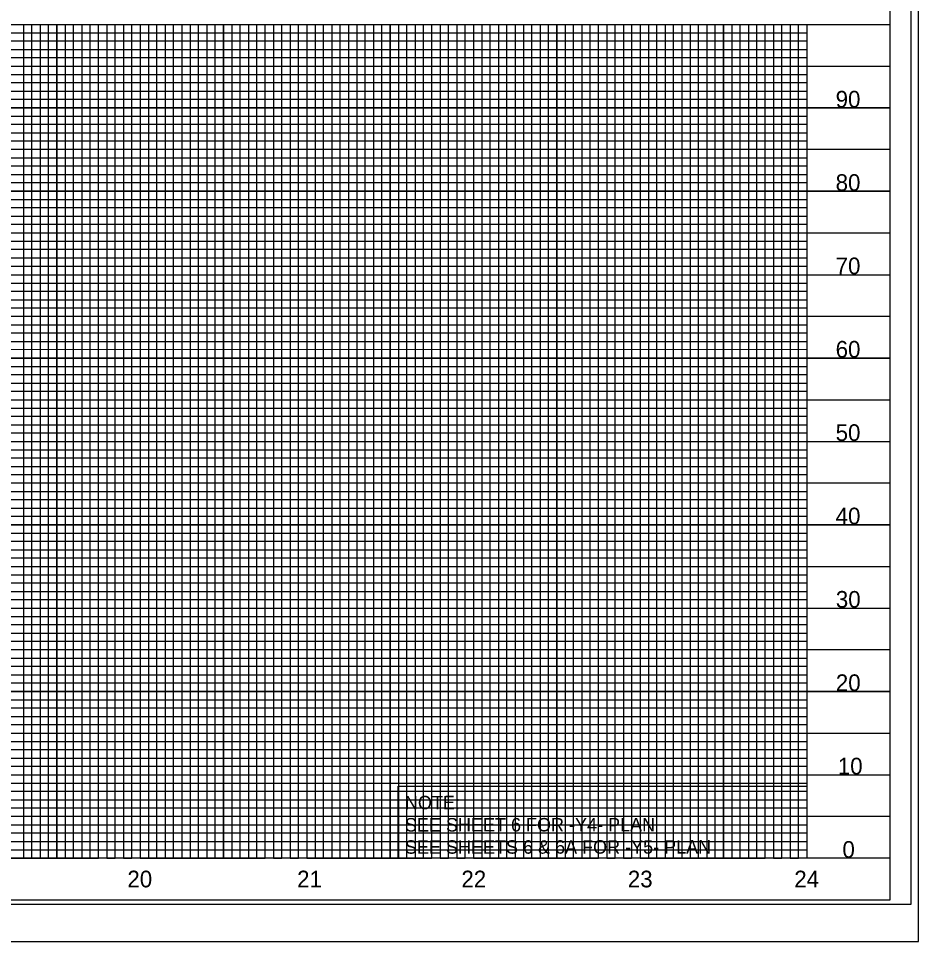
# Model space of a CAD drawing. Extents: x 2186391 to 2188300, y 74582 to 75682.
# Drawn here: x 2187535 to 2188075, y 74582 to 75136 of the extents above; entities that cross this region are included whole.
import ezdxf

# ---------------------------------------------------------------- set-up
doc = ezdxf.new("R2010")
doc.units = 0
for name, color, linetype in [('Exist Structure Minor Culvert Topo', 7, 'Continuous'), ('Exist Structure Minor Culvert Topo Terminator', 7, 'Continuous'), ('Old_Level_1', 7, 'Continuous'), ('Old_Level_11', 7, 'Continuous'), ('Old_Level_2', 7, 'Continuous'), ('Old_Level_3', 7, 'Continuous'), ('Scratch_Level_0', 7, 'Continuous'), ('Sheet Border Standard 30in CELL', 7, 'Continuous'), ('Sheet Cutting Line CELL', 7, 'Continuous'), ('Sheet Plot Border Outside CELL', 7, 'Continuous'), ('Sheet Sticker Exception Certification CELL', 7, 'Continuous'), ('Sheet Sticker Incomplete CELL', 7, 'Continuous'), ('Sheet Sticker Preliminary CELL', 7, 'Continuous')]:
    doc.layers.add(name, color=color, linetype=linetype)

msp = doc.modelspace()

# ---------------------------------------------------------------- linework, layer by layer
at = {"layer": 'Exist Structure Minor Culvert Topo Terminator'}
msp.add_lwpolyline([(2187762.5, 74675.46), (2188007.69, 74675.46), (2188007.69, 74632.28), (2187762.5, 74632.28)], close=True, dxfattribs=at)
at = {"layer": 'Old_Level_11'}
for p, q in [((2186557.69, 75132.28), (2188057.58, 75132.28)), ((2187557.69, 75132.28), (2187557.69, 74632.28)), ((2187607.69, 75132.28), (2187607.69, 74632.28)), ((2187657.69, 75132.28), (2187657.69, 74632.28)), ((2187707.69, 75132.28), (2187707.69, 74632.28)), ((2187757.69, 75132.28), (2187757.69, 74632.28)), ((2187807.69, 75132.28), (2187807.69, 74632.28)), ((2187857.69, 75132.28), (2187857.69, 74632.28)), ((2187907.69, 75132.28), (2187907.69, 74632.28)), ((2187957.69, 75132.28), (2187957.69, 74632.28)), ((2188007.69, 75132.28), (2188007.69, 74632.28)), ((2186557.69, 75082.28), (2188057.58, 75082.28)), ((2186557.69, 75032.28), (2188057.58, 75032.28)), ((2186557.69, 74982.28), (2188057.58, 74982.28)), ((2186557.69, 74932.28), (2188057.58, 74932.28)), ((2186557.69, 74882.28), (2188057.58, 74882.28)), ((2186557.69, 74832.28), (2188057.58, 74832.28)), ((2186557.69, 74782.28), (2188057.58, 74782.28)), ((2186557.69, 74732.28), (2188057.58, 74732.28)), ((2186557.69, 74682.28), (2188057.58, 74682.28))]:
    msp.add_line(p, q, dxfattribs=at)
at = {"layer": 'Old_Level_2'}
for points in [[(2187532.69, 74632.28), (2187582.69, 74632.28), (2187582.69, 75132.28), (2187632.69, 75132.28), (2187632.69, 74632.28), (2187682.69, 74632.28), (2187682.69, 75132.28), (2187732.69, 75132.28), (2187732.69, 74632.28), (2187782.69, 74632.28), (2187782.69, 75132.28), (2187832.69, 75132.28), (2187832.69, 74632.28), (2187882.69, 74632.28), (2187882.69, 75132.28), (2187932.69, 75132.28), (2187932.69, 74632.28), (2187982.69, 74632.28), (2187982.69, 75132.28)], [(2186557.69, 75107.28), (2188057.69, 75107.28)], [(2188057.69, 75057.28), (2186557.69, 75057.28), (2186557.69, 75007.28), (2188057.69, 75007.28)], [(2188057.69, 74957.28), (2186557.69, 74957.28), (2186557.69, 74907.28), (2188057.69, 74907.28)], [(2188057.69, 74857.28), (2186557.69, 74857.28), (2186557.69, 74807.28), (2188057.69, 74807.28)], [(2188057.69, 74757.28), (2186557.69, 74757.28), (2186557.69, 74707.28), (2188057.69, 74707.28)], [(2188057.69, 74657.28), (2186557.69, 74657.28)]]:
    msp.add_lwpolyline(points, dxfattribs=at)
at = {"layer": 'Scratch_Level_0'}
msp.add_line((2186390.69, 74582.28), (2188074.69, 74582.28), dxfattribs=at)
at = {"layer": 'Sheet Border Standard 30in CELL'}
msp.add_lwpolyline([(2186607.69, 75132.28), (2188007.69, 75132.28), (2188007.69, 74632.28), (2186607.69, 74632.28)], close=True, dxfattribs=at)
msp.add_lwpolyline([(2186607.69, 75132.28), (2188007.69, 75132.28), (2188007.69, 74632.28), (2186607.69, 74632.28)], close=True, dxfattribs=at)
at = {"layer": 'Sheet Cutting Line CELL'}
for p, q in [((2186557.69, 75132.28), (2188057.69, 75132.28)), ((2188057.69, 74632.28), (2186557.69, 74632.28)), ((2186557.69, 74607.28), (2188057.69, 74607.28))]:
    msp.add_line(p, q, dxfattribs=at)
msp.add_lwpolyline([(2188057.69, 75657.28), (2186557.69, 75657.28), (2186557.69, 74607.28), (2188057.69, 74607.28)], close=True, dxfattribs=at)
at = {"layer": 'Sheet Plot Border Outside CELL'}
for p, q in [((2186607.69, 75127.28), (2188007.69, 75127.28)), ((2188007.69, 75122.28), (2186607.69, 75122.28)), ((2186607.69, 75117.28), (2188007.69, 75117.28)), ((2188007.69, 75112.28), (2186607.69, 75112.28)), ((2186607.69, 75102.28), (2188007.69, 75102.28)), ((2188007.69, 75097.28), (2186607.69, 75097.28)), ((2186607.69, 75092.28), (2188007.69, 75092.28)), ((2188007.69, 75087.28), (2186607.69, 75087.28)), ((2186607.69, 75077.28), (2188007.69, 75077.28)), ((2188007.69, 75072.28), (2186607.69, 75072.28)), ((2186607.69, 75067.28), (2188007.69, 75067.28)), ((2188007.69, 75062.28), (2186607.69, 75062.28)), ((2186607.69, 75052.28), (2188007.69, 75052.28)), ((2188007.69, 75047.28), (2186607.69, 75047.28)), ((2186607.69, 75042.28), (2188007.69, 75042.28)), ((2188007.69, 75037.28), (2186607.69, 75037.28)), ((2186607.69, 75027.28), (2188007.69, 75027.28)), ((2188007.69, 75022.28), (2186607.69, 75022.28)), ((2186607.69, 75017.28), (2188007.69, 75017.28)), ((2188007.69, 75012.28), (2186607.69, 75012.28)), ((2186607.69, 75002.28), (2188007.69, 75002.28)), ((2188007.69, 74997.28), (2186607.69, 74997.28)), ((2186607.69, 74992.28), (2188007.69, 74992.28)), ((2188007.69, 74987.28), (2186607.69, 74987.28)), ((2186607.69, 74977.28), (2188007.69, 74977.28)), ((2188007.69, 74972.28), (2186607.69, 74972.28)), ((2186607.69, 74967.28), (2188007.69, 74967.28)), ((2188007.69, 74962.28), (2186607.69, 74962.28)), ((2186607.69, 74952.28), (2188007.69, 74952.28)), ((2188007.69, 74947.28), (2186607.69, 74947.28)), ((2186607.69, 74942.28), (2188007.69, 74942.28)), ((2188007.69, 74937.28), (2186607.69, 74937.43)), ((2186607.69, 74927.28), (2188007.69, 74927.28)), ((2188007.69, 74922.28), (2186607.69, 74922.28)), ((2186607.69, 74917.28), (2188007.69, 74917.28)), ((2188007.69, 74912.28), (2186607.69, 74912.28)), ((2186607.69, 74902.28), (2188007.69, 74902.28)), ((2188007.69, 74897.28), (2186607.69, 74897.28)), ((2186607.69, 74892.28), (2188007.69, 74892.28)), ((2188007.69, 74887.28), (2186607.69, 74887.28)), ((2186607.69, 74877.28), (2188007.69, 74877.28)), ((2188007.69, 74872.28), (2186607.69, 74872.28)), ((2186607.69, 74867.28), (2188007.69, 74867.28)), ((2188007.69, 74862.28), (2186607.69, 74862.28)), ((2186607.69, 74852.28), (2188007.69, 74852.28)), ((2188007.69, 74847.28), (2186607.69, 74847.28)), ((2186607.69, 74842.28), (2188007.69, 74842.28)), ((2188007.69, 74837.28), (2186607.69, 74837.28)), ((2186607.69, 74827.28), (2188007.69, 74827.28)), ((2188007.69, 74822.28), (2186607.69, 74822.28)), ((2186607.69, 74817.28), (2188007.69, 74817.28)), ((2188007.69, 74812.28), (2186607.69, 74812.28)), ((2186607.69, 74802.28), (2188007.69, 74802.28)), ((2188007.69, 74797.28), (2186607.69, 74797.28)), ((2186607.69, 74792.28), (2188007.69, 74792.28)), ((2188007.69, 74787.28), (2186607.69, 74787.28)), ((2186607.69, 74777.28), (2188007.69, 74777.28)), ((2188007.69, 74772.28), (2186607.69, 74772.28)), ((2186607.69, 74767.28), (2188007.69, 74767.28)), ((2188007.69, 74762.28), (2186607.69, 74762.28)), ((2186607.69, 74752.28), (2188007.69, 74752.28)), ((2188007.69, 74747.28), (2186607.69, 74747.28)), ((2186607.69, 74742.28), (2188007.69, 74742.28)), ((2188007.69, 74737.28), (2186607.69, 74737.28)), ((2186607.69, 74727.28), (2188007.69, 74727.28)), ((2188007.69, 74722.28), (2186607.69, 74722.28)), ((2186607.69, 74717.28), (2188007.69, 74717.28)), ((2188007.69, 74712.28), (2186607.69, 74712.28)), ((2186607.69, 74702.28), (2188007.69, 74702.28)), ((2188007.69, 74697.28), (2186607.69, 74697.28)), ((2186607.69, 74692.28), (2188007.69, 74692.28)), ((2188007.69, 74687.28), (2186607.69, 74687.28)), ((2186607.69, 74677.28), (2188007.69, 74677.28)), ((2188007.69, 74672.28), (2186607.69, 74672.28)), ((2186607.69, 74667.28), (2188007.69, 74667.28)), ((2188007.69, 74662.28), (2186607.69, 74662.28)), ((2186607.69, 74652.28), (2188007.69, 74652.28)), ((2188007.69, 74647.28), (2186607.69, 74647.28)), ((2186607.69, 74642.28), (2188007.69, 74642.28)), ((2186607.69, 74637.28), (2188007.69, 74637.28)), ((2188007.69, 74637.28), (2188007.69, 74637.28))]:
    msp.add_line(p, q, dxfattribs=at)
for points in [[(2187527.69, 75132.28), (2187537.69, 75132.28), (2187537.69, 74632.28), (2187542.69, 74632.28), (2187542.69, 75132.28), (2187547.69, 75132.28), (2187547.69, 74632.28), (2187552.69, 74632.28), (2187552.69, 75132.28), (2187562.69, 75132.28), (2187562.69, 74632.28), (2187567.69, 74632.28), (2187567.69, 75132.28), (2187572.69, 75132.28), (2187572.69, 74632.28), (2187577.69, 74632.28), (2187577.69, 75132.28), (2187587.69, 75132.28), (2187587.69, 74632.28), (2187592.69, 74632.28), (2187592.69, 75132.28), (2187597.69, 75132.28), (2187597.69, 74632.28), (2187602.69, 74632.28), (2187602.69, 75132.28), (2187612.69, 75132.28), (2187612.69, 74632.28), (2187617.69, 74632.28), (2187617.69, 75132.28), (2187622.69, 75132.28), (2187622.69, 74632.28), (2187627.69, 74632.28), (2187627.69, 75132.28), (2187637.69, 75132.28), (2187637.69, 74632.28), (2187642.69, 74632.28), (2187642.69, 75132.28), (2187647.69, 75132.28), (2187647.69, 74632.28), (2187652.69, 74632.28), (2187652.69, 75132.28), (2187662.69, 75132.28), (2187662.69, 74632.28), (2187667.69, 74632.28), (2187667.69, 75132.28), (2187672.69, 75132.28), (2187672.69, 74632.28), (2187677.69, 74632.28), (2187677.69, 75132.28), (2187687.69, 75132.28), (2187687.69, 74632.28), (2187692.69, 74632.28), (2187692.69, 75132.28), (2187697.69, 75132.28), (2187697.69, 74632.28), (2187702.69, 74632.28), (2187702.69, 75132.28), (2187712.69, 75132.28), (2187712.69, 74632.28), (2187717.69, 74632.28), (2187717.69, 75132.28), (2187722.69, 75132.28), (2187722.69, 74632.28), (2187727.69, 74632.28), (2187727.69, 75132.28), (2187737.69, 75132.28), (2187737.69, 74632.28), (2187742.69, 74632.28), (2187742.69, 75132.28), (2187747.69, 75132.28), (2187747.69, 74632.28)], [(2187747.69, 74632.28), (2187752.69, 74632.28), (2187752.69, 75132.28), (2187762.69, 75132.28), (2187762.69, 74632.28), (2187767.69, 74632.28), (2187767.69, 75132.28), (2187772.69, 75132.28), (2187772.69, 74632.28), (2187777.69, 74632.28), (2187777.69, 75132.28), (2187787.69, 75132.28), (2187787.69, 74632.28), (2187792.69, 74632.28), (2187792.69, 75132.28), (2187797.69, 75132.28), (2187797.69, 74632.28), (2187802.69, 74632.28), (2187802.69, 75132.28), (2187812.69, 75132.28), (2187812.69, 74632.28), (2187817.69, 74632.28), (2187817.69, 75132.28), (2187822.69, 75132.28), (2187822.69, 74632.28), (2187827.69, 74632.28), (2187827.69, 75132.28), (2187837.69, 75132.28), (2187837.69, 74632.28), (2187842.69, 74632.28), (2187842.69, 75132.28), (2187847.69, 75132.28), (2187847.69, 74632.28), (2187852.69, 74632.28), (2187852.69, 75132.28), (2187862.69, 75132.28), (2187862.69, 74632.28), (2187867.69, 74632.28), (2187867.69, 75132.28), (2187872.69, 75132.28), (2187872.69, 74632.28), (2187877.69, 74632.28), (2187877.69, 75132.28), (2187887.69, 75132.28), (2187887.69, 74632.28), (2187892.69, 74632.28), (2187892.69, 75132.28), (2187897.69, 75132.28), (2187897.69, 74632.28), (2187902.69, 74632.28), (2187902.69, 75132.28), (2187912.69, 75132.28), (2187912.69, 74632.28), (2187917.69, 74632.28), (2187917.69, 75132.28), (2187922.69, 75132.28), (2187922.69, 74632.28), (2187927.69, 74632.28), (2187927.69, 75132.28), (2187937.69, 75132.28), (2187937.69, 74632.28), (2187942.69, 74632.28), (2187942.69, 75132.28), (2187947.69, 75132.28), (2187947.69, 74632.28), (2187952.69, 74632.28), (2187952.69, 75132.28), (2187962.69, 75132.28), (2187962.69, 74632.28), (2187967.69, 74632.28), (2187967.69, 75132.28), (2187972.69, 75132.28), (2187972.69, 74632.28), (2187977.69, 74632.28), (2187977.69, 75132.28), (2187987.69, 75132.28), (2187987.69, 74632.28), (2187992.69, 74632.28), (2187992.69, 75132.28), (2187997.69, 75132.28), (2187997.69, 74632.28), (2188002.69, 74632.28), (2188002.69, 75132.28), (2188007.69, 75132.28)]]:
    msp.add_lwpolyline(points, dxfattribs=at)
at = {"layer": 'Sheet Sticker Exception Certification CELL'}
for p, q in [((2187557.69, 75132.28), (2187607.69, 75132.28)), ((2187657.69, 75132.28), (2187707.69, 75132.28)), ((2187757.69, 75132.28), (2187807.69, 75132.28)), ((2187857.69, 75132.28), (2187907.69, 75132.28)), ((2187957.69, 75132.28), (2188007.69, 75132.28)), ((2187957.69, 74632.28), (2187957.69, 74632.28))]:
    msp.add_line(p, q, dxfattribs=at)
for points in [[(2187507.69, 74632.28), (2187557.69, 74632.28), (2187557.69, 75132.28), (2187607.69, 75132.28), (2187607.69, 74632.28), (2187657.69, 74632.28), (2187657.69, 75132.28), (2187707.69, 75132.28), (2187707.69, 74632.28), (2187757.69, 74632.28), (2187757.69, 75132.28), (2187807.69, 75132.28), (2187807.69, 74632.28), (2187857.69, 74632.28), (2187857.69, 75132.28), (2187907.69, 75132.28), (2187907.69, 74632.28), (2187957.69, 74632.28), (2187957.69, 74632.28), (2187957.69, 75132.28), (2188007.69, 75132.28), (2188007.69, 74632.28)], [(2188057.69, 75082.28), (2186557.69, 75082.28)], [(2188057.69, 75032.28), (2186557.69, 75032.28), (2186557.69, 74982.28), (2188057.69, 74982.28)], [(2188057.69, 74932.28), (2186557.69, 74932.28), (2186557.69, 74882.28), (2188057.69, 74882.28)], [(2188057.69, 74832.28), (2186557.69, 74832.28), (2186557.69, 74782.28), (2188057.69, 74782.28)], [(2188057.69, 74732.28), (2186557.69, 74732.28), (2186557.69, 74732.28), (2186557.69, 74682.28), (2188057.69, 74682.28)], [(2188057.69, 74632.28), (2186557.69, 74632.28)]]:
    msp.add_lwpolyline(points, dxfattribs=at)
at = {"layer": 'Sheet Sticker Incomplete CELL'}
msp.add_lwpolyline([(2186390.69, 74582.28), (2188074.69, 74582.28), (2188074.69, 75682.28), (2186390.69, 75682.28)], close=True, dxfattribs=at)
at = {"layer": 'Sheet Sticker Preliminary CELL'}
msp.add_lwpolyline([(2186403.69, 74604.73), (2188070.19, 74604.73), (2188070.19, 75659.83), (2186403.69, 75659.83)], close=True, dxfattribs=at)

# ---------------------------------------------------------------- texts
at = {"layer": 'Exist Structure Minor Culvert Topo'}
for s, height, p in [('NOTE:', 8.077, (2187766.57, 74661.59)), ('SEE SHEET 6 FOR -Y4- PLAN', 8.0769, (2187766.58, 74648.27)), ('SEE SHEETS 6 & 6A FOR -Y5- PLAN', 8.0769, (2187766.59, 74634.94))]:
    msp.add_text(s, height=height, rotation=0.023, dxfattribs=at).set_placement(p)
at = {"layer": 'Old_Level_1'}
for s, p in [('20', (2187600.08, 74614.78)), ('21', (2187701.91, 74614.78)), ('22', (2187800.46, 74614.78)), ('23', (2187900.3, 74614.78)), ('24', (2188000.14, 74614.78))]:
    msp.add_text(s, height=10, dxfattribs=at).set_placement(p)
at = {"layer": 'Old_Level_3'}
for s, p in [('90', (2188024.96, 75082.53)), ('80', (2188024.96, 75032.53)), ('70', (2188024.96, 74982.53)), ('60', (2188024.96, 74932.53)), ('50', (2188024.96, 74882.53)), ('40', (2188024.96, 74832.53)), ('30', (2188025.08, 74782.53)), ('20', (2188025.08, 74732.53)), ('10', (2188026.27, 74682.53)), ('0', (2188029.03, 74632.53))]:
    msp.add_text(s, height=10, dxfattribs=at).set_placement(p)

doc.saveas('drawing.dxf')
